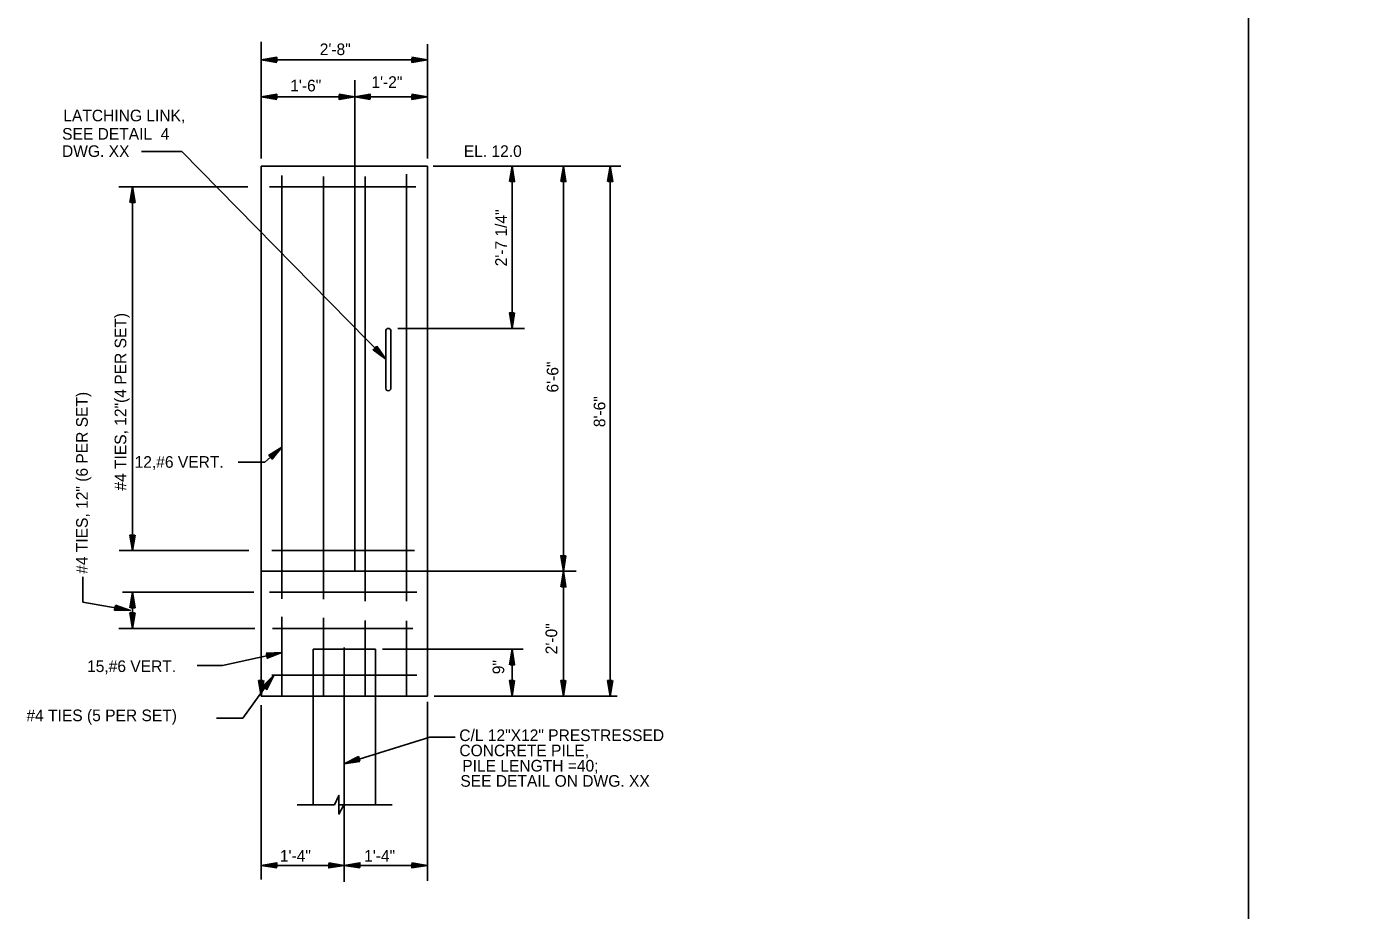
# Model space of a CAD drawing. Extents: x -48 to 108, y -5 to 100.
# Drawn here: x -37.91 to 4.59, y 37.1 to 65.46 of the extents above; entities that cross this region are included whole.
import ezdxf

# ---------------------------------------------------------------- set-up
doc = ezdxf.new("R2010")
doc.units = 0
for name, color, linetype in [('Level 1', 7, 'Continuous'), ('Level 13', 7, 'Continuous'), ('Level 22', 7, 'Continuous'), ('Level 25', 7, 'Continuous'), ('Level 50', 7, 'Continuous')]:
    doc.layers.add(name, color=color, linetype=linetype)

msp = doc.modelspace()

# ---------------------------------------------------------------- linework, layer by layer
at = {"layer": 'Level 1'}
msp.add_lwpolyline([(1.292, 75.958), (107.958, 75.958), (107.958, 1.292), (1.292, 1.292)], close=True, dxfattribs=at)
at = {"layer": 'Level 13'}
msp.add_lwpolyline([(-28.037, 40.491), (-27.888, 40.791), (-27.888, 40.192), (-27.738, 40.491)], dxfattribs=at)
at = {"layer": 'Level 22'}
for p, q in [((-30.384, 61.219), (-30.384, 64.963)), ((-25.051, 63.763), (-25.051, 64.889)), ((-30.384, 64.383), (-25.051, 64.383)), ((-25.051, 61.219), (-25.051, 63.763)), ((-27.384, 60.978), (-27.384, 63.736)), ((-30.384, 63.199), (-27.384, 63.199)), ((-27.384, 63.199), (-25.051, 63.199)), ((-34.226, 61.442), (-32.932, 61.442)), ((-32.932, 61.442), (-26.388, 54.788)), ((-24.871, 60.978), (-18.848, 60.978)), ((-22.338, 55.769), (-22.338, 60.978)), ((-20.691, 47.978), (-20.691, 60.978)), ((-19.187, 43.978), (-19.187, 60.978)), ((-34.948, 60.311), (-30.817, 60.311)), ((-34.51, 48.644), (-34.51, 60.311)), ((-26.388, 53.853), (-26.388, 55.686)), ((-26.221, 53.853), (-26.221, 55.686)), ((-25.998, 55.769), (-21.938, 55.769)), ((-30.271, 51.475), (-29.718, 51.965)), ((-31.126, 51.475), (-30.271, 51.475)), ((-34.94, 48.644), (-30.778, 48.644)), ((-36.106, 46.987), (-36.106, 47.797)), ((-25.051, 47.978), (-20.277, 47.978)), ((-20.691, 43.978), (-20.691, 47.978)), ((-34.832, 47.311), (-30.624, 47.311)), ((-34.51, 46.144), (-34.51, 47.311)), ((-36.106, 46.987), (-34.581, 46.725)), ((-34.948, 46.144), (-30.585, 46.144)), ((-31.628, 44.96), (-29.718, 45.377)), ((-26.493, 45.478), (-21.976, 45.478)), ((-22.338, 43.978), (-22.338, 45.478)), ((-32.438, 44.96), (-31.628, 44.96)), ((-30.971, 43.27), (-29.973, 44.644)), ((-25.051, 38.051), (-25.051, 43.796)), ((-24.833, 43.978), (-18.964, 43.978)), ((-30.384, 38.088), (-30.384, 43.683)), ((-31.821, 43.27), (-30.971, 43.27)), ((-24.977, 42.66), (-27.718, 41.808)), ((-24.977, 42.66), (-24.165, 42.66)), ((-29.234, 40.491), (-28.037, 40.491)), ((-27.888, 40.491), (-26.177, 40.491)), ((-30.384, 38.546), (-27.718, 38.546)), ((-27.718, 38.546), (-25.051, 38.546))]:
    msp.add_line(p, q, dxfattribs=at)
for centre, start, end in [((-26.304, 55.686), 0, 180), ((-26.304, 53.853), 176.7184, 0)]:
    msp.add_arc(centre, 0.0833, start, end, dxfattribs=at)
at = {"layer": 'Level 25'}
for p, q in [((-30.384, 43.978), (-30.384, 60.978)), ((-30.384, 60.978), (-25.051, 60.978)), ((-27.384, 47.978), (-27.384, 60.978)), ((-25.051, 43.978), (-25.051, 60.978)), ((-29.718, 47.1), (-29.718, 60.678)), ((-28.384, 47.081), (-28.384, 60.643)), ((-27.051, 47.025), (-27.051, 60.643)), ((-25.718, 47.025), (-25.718, 60.713)), ((-30.116, 60.311), (-25.426, 60.311)), ((-30.044, 48.644), (-25.461, 48.644)), ((-30.384, 47.978), (-25.051, 47.978)), ((-30.116, 47.311), (-25.39, 47.311)), ((-29.718, 43.978), (-29.718, 46.518)), ((-28.384, 43.978), (-28.384, 46.481)), ((-27.051, 43.978), (-27.051, 46.405)), ((-25.718, 43.978), (-25.718, 46.387)), ((-30.017, 46.144), (-25.524, 46.144)), ((-27.718, 38.013), (-27.718, 45.531)), ((-28.718, 45.478), (-26.718, 45.478)), ((-28.718, 43.978), (-28.718, 45.478)), ((-26.718, 43.978), (-26.718, 45.478)), ((-30.044, 44.644), (-25.39, 44.644)), ((-30.384, 43.978), (-25.051, 43.978)), ((-28.718, 40.491), (-28.718, 43.978)), ((-26.718, 40.491), (-26.718, 43.978))]:
    msp.add_line(p, q, dxfattribs=at)
at = {"layer": 'Level 50'}
for p, q in [((-30.384, 64.383), (-30.384, 64.383)), ((-30.246, 64.383), (-30.246, 64.383)), ((-25.19, 64.383), (-25.19, 64.383)), ((-25.19, 64.383), (-25.19, 64.383)), ((-25.051, 64.383), (-25.051, 64.383)), ((-25.051, 64.383), (-25.051, 64.383)), ((-30.384, 63.199), (-30.384, 63.199)), ((-30.246, 63.199), (-30.246, 63.199)), ((-27.523, 63.199), (-27.523, 63.199)), ((-27.384, 63.199), (-27.384, 63.199)), ((-27.384, 63.199), (-27.384, 63.199)), ((-27.246, 63.199), (-27.246, 63.199)), ((-25.19, 63.199), (-25.19, 63.199)), ((-25.051, 63.199), (-25.051, 63.199)), ((-22.338, 60.978), (-22.338, 60.978)), ((-22.338, 60.978), (-22.338, 60.978)), ((-22.338, 60.839), (-22.338, 60.839)), ((-22.338, 60.839), (-22.338, 60.839)), ((-20.691, 60.978), (-20.691, 60.978)), ((-20.691, 60.839), (-20.691, 60.839)), ((-19.187, 60.978), (-19.187, 60.978)), ((-19.187, 60.839), (-19.187, 60.839)), ((-34.51, 60.311), (-34.51, 60.311)), ((-34.51, 60.172), (-34.51, 60.172)), ((-22.338, 55.908), (-22.338, 55.908)), ((-22.338, 55.769), (-22.338, 55.769)), ((-26.485, 54.887), (-26.485, 54.887)), ((-26.388, 54.788), (-26.388, 54.788)), ((-29.821, 51.873), (-29.821, 51.873)), ((-29.718, 51.965), (-29.718, 51.965)), ((-34.51, 48.783), (-34.51, 48.783)), ((-34.51, 48.644), (-34.51, 48.644)), ((-20.691, 48.116), (-20.691, 48.116)), ((-20.691, 47.978), (-20.691, 47.978)), ((-20.691, 47.978), (-20.691, 47.978)), ((-20.691, 47.839), (-20.691, 47.839)), ((-34.51, 47.311), (-34.51, 47.311)), ((-34.51, 47.172), (-34.51, 47.172)), ((-34.718, 46.748), (-34.718, 46.748)), ((-34.581, 46.725), (-34.581, 46.725)), ((-34.51, 46.283), (-34.51, 46.283)), ((-34.51, 46.144), (-34.51, 46.144)), ((-29.853, 45.347), (-29.853, 45.347)), ((-29.853, 45.347), (-29.853, 45.347)), ((-29.718, 45.377), (-29.718, 45.377)), ((-29.718, 45.377), (-29.718, 45.377)), ((-22.338, 45.478), (-22.338, 45.478)), ((-22.338, 45.339), (-22.338, 45.339)), ((-29.973, 44.644), (-29.973, 44.644)), ((-30.054, 44.532), (-30.054, 44.532)), ((-30.384, 44.116), (-30.384, 44.116)), ((-30.384, 43.978), (-30.384, 43.978)), ((-22.338, 44.116), (-22.338, 44.116)), ((-22.338, 43.978), (-22.338, 43.978)), ((-20.691, 44.116), (-20.691, 44.116)), ((-20.691, 43.978), (-20.691, 43.978)), ((-19.187, 44.116), (-19.187, 44.116)), ((-19.187, 43.978), (-19.187, 43.978)), ((-27.718, 41.808), (-27.718, 41.808)), ((-27.585, 41.849), (-27.585, 41.849)), ((-30.384, 38.546), (-30.384, 38.546)), ((-30.246, 38.546), (-30.246, 38.546)), ((-27.856, 38.546), (-27.856, 38.546)), ((-27.718, 38.546), (-27.718, 38.546)), ((-27.718, 38.546), (-27.718, 38.546)), ((-27.579, 38.546), (-27.579, 38.546)), ((-25.19, 38.546), (-25.19, 38.546)), ((-25.051, 38.546), (-25.051, 38.546))]:
    msp.add_line(p, q, dxfattribs=at)
for points in [[(-29.886, 64.301), (-30.384, 64.383), (-29.886, 64.466), (-29.886, 64.325), (-30.246, 64.383), (-29.907, 64.439), (-29.907, 64.349), (-30.112, 64.383), (-29.928, 64.413), (-29.928, 64.375), (-29.974, 64.383)], [(-25.55, 64.466), (-25.051, 64.383), (-25.55, 64.301), (-25.55, 64.442), (-25.19, 64.383), (-25.528, 64.327), (-25.528, 64.418), (-25.323, 64.383), (-25.507, 64.354), (-25.507, 64.391), (-25.462, 64.383)], [(-25.55, 64.466), (-25.051, 64.383), (-25.55, 64.301), (-25.55, 64.442), (-25.19, 64.383), (-25.528, 64.327), (-25.528, 64.418), (-25.323, 64.383), (-25.507, 64.354), (-25.507, 64.391), (-25.462, 64.383)], [(-29.886, 63.117), (-30.384, 63.199), (-29.886, 63.282), (-29.886, 63.141), (-30.246, 63.199), (-29.907, 63.255), (-29.907, 63.165), (-30.112, 63.199), (-29.928, 63.229), (-29.928, 63.191), (-29.974, 63.199)], [(-27.883, 63.282), (-27.384, 63.199), (-27.883, 63.117), (-27.883, 63.258), (-27.523, 63.199), (-27.862, 63.143), (-27.862, 63.234), (-27.656, 63.199), (-27.84, 63.17), (-27.84, 63.207), (-27.795, 63.199)], [(-26.886, 63.117), (-27.384, 63.199), (-26.886, 63.282), (-26.886, 63.141), (-27.246, 63.199), (-26.907, 63.255), (-26.907, 63.165), (-27.112, 63.199), (-26.928, 63.229), (-26.928, 63.191), (-26.974, 63.199)], [(-25.55, 63.282), (-25.051, 63.199), (-25.55, 63.117), (-25.55, 63.258), (-25.19, 63.199), (-25.528, 63.143), (-25.528, 63.234), (-25.323, 63.199), (-25.507, 63.17), (-25.507, 63.207), (-25.462, 63.199)], [(-22.42, 60.479), (-22.338, 60.978), (-22.255, 60.479), (-22.396, 60.479), (-22.338, 60.839), (-22.282, 60.5), (-22.372, 60.5), (-22.338, 60.706), (-22.308, 60.522), (-22.346, 60.522), (-22.338, 60.567)], [(-22.42, 60.479), (-22.338, 60.978), (-22.255, 60.479), (-22.396, 60.479), (-22.338, 60.839), (-22.282, 60.5), (-22.372, 60.5), (-22.338, 60.706), (-22.308, 60.522), (-22.346, 60.522), (-22.338, 60.567)], [(-20.773, 60.479), (-20.691, 60.978), (-20.608, 60.479), (-20.749, 60.479), (-20.691, 60.839), (-20.635, 60.5), (-20.725, 60.5), (-20.691, 60.706), (-20.661, 60.522), (-20.699, 60.522), (-20.691, 60.567)], [(-19.27, 60.479), (-19.187, 60.978), (-19.104, 60.479), (-19.246, 60.479), (-19.187, 60.839), (-19.131, 60.5), (-19.222, 60.5), (-19.187, 60.706), (-19.158, 60.522), (-19.195, 60.522), (-19.187, 60.567)], [(-34.593, 59.812), (-34.51, 60.311), (-34.428, 59.812), (-34.569, 59.812), (-34.51, 60.172), (-34.454, 59.834), (-34.545, 59.834), (-34.51, 60.039), (-34.481, 59.855), (-34.518, 59.855), (-34.51, 59.9)], [(-22.255, 56.268), (-22.338, 55.769), (-22.42, 56.268), (-22.279, 56.268), (-22.338, 55.908), (-22.394, 56.247), (-22.303, 56.247), (-22.338, 56.041), (-22.367, 56.225), (-22.33, 56.225), (-22.338, 56.18)], [(-26.678, 55.202), (-26.388, 54.788), (-26.796, 55.086), (-26.695, 55.185), (-26.485, 54.887), (-26.762, 55.089), (-26.698, 55.153), (-26.578, 54.982), (-26.728, 55.093), (-26.702, 55.119), (-26.676, 55.081)], [(-30.146, 51.696), (-29.718, 51.965), (-30.036, 51.573), (-30.13, 51.678), (-29.821, 51.873), (-30.038, 51.607), (-30.098, 51.675), (-29.921, 51.785), (-30.039, 51.641), (-30.064, 51.669), (-30.025, 51.693)], [(-34.428, 49.143), (-34.51, 48.644), (-34.593, 49.143), (-34.452, 49.143), (-34.51, 48.783), (-34.566, 49.122), (-34.476, 49.122), (-34.51, 48.916), (-34.54, 49.1), (-34.502, 49.1), (-34.51, 49.055)], [(-20.608, 48.476), (-20.691, 47.978), (-20.773, 48.476), (-20.632, 48.476), (-20.691, 48.116), (-20.747, 48.455), (-20.656, 48.455), (-20.691, 48.25), (-20.72, 48.434), (-20.683, 48.434), (-20.691, 48.388)], [(-20.773, 47.479), (-20.691, 47.978), (-20.608, 47.479), (-20.749, 47.479), (-20.691, 47.839), (-20.635, 47.5), (-20.725, 47.5), (-20.691, 47.706), (-20.661, 47.522), (-20.699, 47.522), (-20.691, 47.567)], [(-34.593, 46.812), (-34.51, 47.311), (-34.428, 46.812), (-34.569, 46.812), (-34.51, 47.172), (-34.454, 46.834), (-34.545, 46.834), (-34.51, 47.039), (-34.481, 46.855), (-34.518, 46.855), (-34.51, 46.9)], [(-35.059, 46.891), (-34.581, 46.725), (-35.087, 46.728), (-35.063, 46.867), (-34.718, 46.748), (-35.061, 46.75), (-35.046, 46.84), (-34.849, 46.771), (-35.036, 46.773), (-35.029, 46.81), (-34.986, 46.794)], [(-34.428, 46.643), (-34.51, 46.144), (-34.593, 46.643), (-34.452, 46.643), (-34.51, 46.283), (-34.566, 46.622), (-34.476, 46.622), (-34.51, 46.416), (-34.54, 46.6), (-34.502, 46.6), (-34.51, 46.555)], [(-30.222, 45.351), (-29.718, 45.377), (-30.187, 45.19), (-30.217, 45.328), (-29.853, 45.347), (-30.172, 45.22), (-30.191, 45.309), (-29.983, 45.319), (-30.157, 45.251), (-30.165, 45.287), (-30.119, 45.289)], [(-30.222, 45.351), (-29.718, 45.377), (-30.187, 45.19), (-30.217, 45.328), (-29.853, 45.347), (-30.172, 45.22), (-30.191, 45.309), (-29.983, 45.319), (-30.157, 45.251), (-30.165, 45.287), (-30.119, 45.289)], [(-22.42, 44.979), (-22.338, 45.478), (-22.255, 44.979), (-22.396, 44.979), (-22.338, 45.339), (-22.282, 45), (-22.372, 45), (-22.338, 45.206), (-22.308, 45.022), (-22.346, 45.022), (-22.338, 45.067)], [(-30.333, 44.289), (-29.973, 44.644), (-30.199, 44.192), (-30.313, 44.275), (-30.054, 44.532), (-30.208, 44.225), (-30.281, 44.279), (-30.133, 44.424), (-30.217, 44.258), (-30.247, 44.28), (-30.214, 44.312)], [(-30.302, 44.476), (-30.384, 43.978), (-30.467, 44.476), (-30.326, 44.476), (-30.384, 44.116), (-30.44, 44.455), (-30.35, 44.455), (-30.384, 44.25), (-30.414, 44.434), (-30.376, 44.434), (-30.384, 44.388)], [(-22.255, 44.476), (-22.338, 43.978), (-22.42, 44.476), (-22.279, 44.476), (-22.338, 44.116), (-22.394, 44.455), (-22.303, 44.455), (-22.338, 44.25), (-22.367, 44.434), (-22.33, 44.434), (-22.338, 44.388)], [(-20.608, 44.476), (-20.691, 43.978), (-20.773, 44.476), (-20.632, 44.476), (-20.691, 44.116), (-20.747, 44.455), (-20.656, 44.455), (-20.691, 44.25), (-20.72, 44.434), (-20.683, 44.434), (-20.691, 44.388)], [(-19.104, 44.476), (-19.187, 43.978), (-19.27, 44.476), (-19.128, 44.476), (-19.187, 44.116), (-19.243, 44.455), (-19.152, 44.455), (-19.187, 44.25), (-19.216, 44.434), (-19.179, 44.434), (-19.187, 44.388)], [(-27.217, 41.877), (-27.718, 41.808), (-27.266, 42.035), (-27.224, 41.9), (-27.585, 41.849), (-27.278, 42.003), (-27.251, 41.916), (-27.458, 41.889), (-27.291, 41.971), (-27.28, 41.936), (-27.325, 41.93)], [(-29.886, 38.464), (-30.384, 38.546), (-29.886, 38.629), (-29.886, 38.488), (-30.246, 38.546), (-29.907, 38.602), (-29.907, 38.512), (-30.112, 38.546), (-29.928, 38.576), (-29.928, 38.538), (-29.974, 38.546)], [(-28.216, 38.629), (-27.718, 38.546), (-28.216, 38.464), (-28.216, 38.605), (-27.856, 38.546), (-28.195, 38.49), (-28.195, 38.581), (-27.99, 38.546), (-28.174, 38.517), (-28.174, 38.554), (-28.128, 38.546)], [(-27.219, 38.464), (-27.718, 38.546), (-27.219, 38.629), (-27.219, 38.488), (-27.579, 38.546), (-27.24, 38.602), (-27.24, 38.512), (-27.446, 38.546), (-27.262, 38.576), (-27.262, 38.538), (-27.307, 38.546)], [(-25.55, 38.629), (-25.051, 38.546), (-25.55, 38.464), (-25.55, 38.605), (-25.19, 38.546), (-25.528, 38.49), (-25.528, 38.581), (-25.323, 38.546), (-25.507, 38.517), (-25.507, 38.554), (-25.462, 38.546)]]:
    msp.add_lwpolyline(points, dxfattribs=at)

# ---------------------------------------------------------------- texts
at = {"layer": 'Level 25'}
for s, height, p in [('2\'-8"', 0.3733, (-28.506, 64.537)), ('1\'-2"', 0.3733, (-26.849, 63.485)), ('1\'-6"', 0.3733, (-29.451, 63.373)), ('LATCHING LINK,', 0.37333, (-36.731, 62.413)), ('SEE DETAIL  4', 0.37333, (-36.769, 61.825)), ('DWG. XX', 0.3733, (-36.773, 61.27)), ('EL. 12.0', 0.3733, (-23.884, 61.27)), ('12,#6 VERT.', 0.37333, (-34.444, 51.3)), ('15,#6 VERT.', 0.37333, (-35.969, 44.748)), ('#4 TIES (5 PER SET)', 0.37333, (-37.914, 43.171)), ('C/L 12"X12" PRESTRESSED', 0.37333, (-24.029, 42.533)), ('CONCRETE PILE,', 0.37333, (-24.026, 42.045)), ('PILE LENGTH =40;', 0.37333, (-23.934, 41.556)), ('SEE DETAIL ON DWG. XX', 0.37333, (-23.995, 41.068)), ('1\'-4"', 0.3733, (-29.783, 38.665)), ('1\'-4"', 0.3733, (-27.081, 38.665))]:
    msp.add_text(s, height=height, dxfattribs=at).set_placement(p)
for s, height, p in [('2\'-7 1/4"', 0.3733, (-22.504, 57.762)), ('#4 TIES, 12"(4 PER SET)', 0.37333, (-34.711, 50.567)), ('6\'-6"', 0.3733, (-20.85, 53.714)), ('#4 TIES, 12" (6 PER SET)', 0.37333, (-35.946, 47.898)), ('8\'-6"', 0.3733, (-19.345, 52.602)), ('2\'-0"', 0.3733, (-20.889, 45.317)), ('9"', 0.3733, (-22.588, 44.677))]:
    msp.add_text(s, height=height, rotation=90, dxfattribs=at).set_placement(p)

doc.saveas('drawing.dxf')
